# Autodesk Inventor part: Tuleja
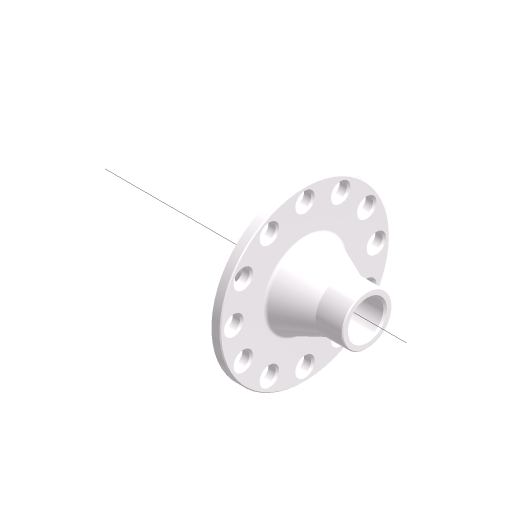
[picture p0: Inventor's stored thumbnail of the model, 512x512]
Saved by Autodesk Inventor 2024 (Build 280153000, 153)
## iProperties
Company: ATC
Shininess: 21.0
Length Units: 11269
Angle Units: 11279
Time Units: 11290
Mass Units: 11283
Length Display Precision: 3
Angle Display Precision: 2
Compacted: True
Created: 2023-03
Part Number: Tuleja
Document SubType Name: Modeling
Designer: Andrzej Jaskulski
Material: Kurs-AJ
Density: 1 g/cm^3
Appearance: Kurs-AJ
Checked By: A.J.
Engr Approved By: Andrzej Jaskulski
Mfg Approved By: Andrzej Jaskulski
Authority: A.J.
Density: 0.0
Volumn: 0.0
Area: 0.0
PropertySet Name: Model Information
Control State: 0
Master: False
Checked Out: False
Title: A.J.: Kurs R2024-MEP
Author: Andrzej Jaskulski
Revision Number: 1/24
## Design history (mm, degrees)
sketch "Zarys"
  geometry: L1 (0, 0)-(45.739, 0) reference; L2 (0, 10)-(60, 10); L3 (60, 10)-(60, 14); L4 (60, 14)-(45, 14); L5 (45, 14)-(25, 22.489); L6 (25, 22.489)-(25, 47.5); L7 (25, 47.5)-(20, 47.5); L8 (20, 47.5)-(20, 15); L9 (20, 15)-(0, 15); L10 (0, 15)-(0, 10) reference
  constraints: 20 end point, 7 parallel, 2 horizontal, 1 perpendicular, 1 vertical
  dimensions: "d0" = 10 distance between parallel lines of L1 L2; "d1" = 15 distance between parallel lines of L9 L1; "d2" = 47.5 distance between parallel lines of L7 L1; "d3" = 60 distance of L2.start L2.end; "d4" = 14 distance between parallel lines of L4 L1; "d5" = 15 distance of L3.end L4.end; "d6" = 20 distance between parallel lines of L8 L10; "d7" = 25 distance between parallel lines of L6 L10; "d8" = 23 deg angle of L5 L4
revolve "Baza" sketch "Zarys" stored, may be unused: angle "d9" = 90 deg
node "Oś"
node "Płaszczyzna symetrii XZ"
sketch "Szkic Rowka"
  geometry: L1 (52.5, 15)-(32.5, 15) reference; L2 (32.5, 47.5)-(32.5, -47.5) reference; L3 (64.5, 0)-(-19.5, 0) reference; C1 r 3.5 at (34, 16.5)
  constraints: 1 centre point
  dimensions: "d12" = 1.5 distance from line of L1 C1.centre; "d13" = 1.5 distance from line of L2 C1.centre; "d14" = 7 diameter of C1
revolve "Podcięcie" sketch "Szkic Rowka" stored, may be unused: angle "d15" = 90 deg
chamfer "Fazy zewnętrzne" distance "d16" = 0.5; stored, may be unused: second distance "d17" = 0.5, angle "d32" = 45 deg
chamfer "Fazy wewnętrzne" distance "d18" = 1; stored, may be unused: second distance "d19" = 1, angle "d33" = 45 deg
fillet "Zaokrąglenie" dims "d31" = 2
sketch "Sketch3"
  geometry: L1 (-66.5, 0)-(66.5, 0) reference; C1 r 22.489 at (0, 0) reference; 1 further point
  constraints: 1 point on line
  dimensions: "d20" = 40 distance of point (-40, 0) C1.centre
hole "Otwór bazowy" sketch "Sketch3" at (-40, 0) diameter "d21" = 9; stored, may be unused: countersink angle "d25" = 90 deg, drill point angle "d27" = 118 deg; dims "d22" = 6, "d23" = 11, "d24" = 2, "d26" = 8
pattern_circular "Szyk otworów" dims angle "d30" = 360 deg
node "Bryła1"
node "Korpusy bryłowe"
node "Korpusy powierzchniowe"
other parameters: "d10" = 0, "d11" = 0
